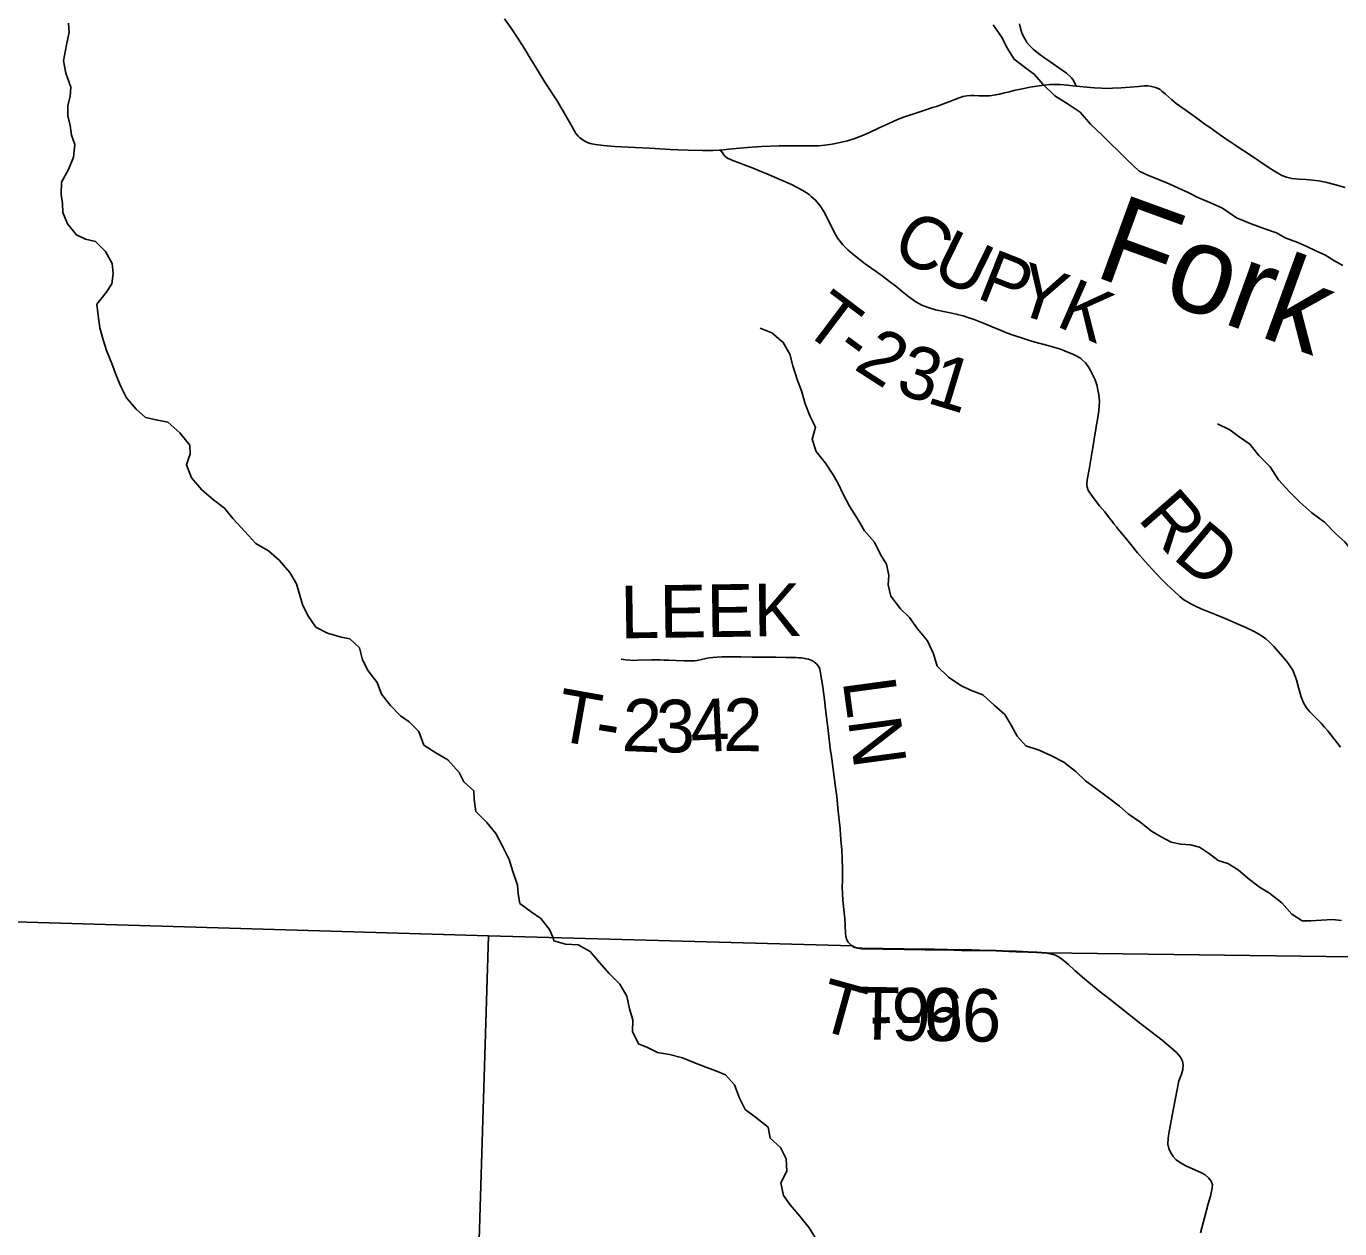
# Model space of a CAD drawing. Extents: x 0 to 34, y 0 to 22.
# Drawn here: x 3.856 to 5.272, y 15.28 to 16.577 of the extents above; entities that cross this region are included whole.
import ezdxf

# ---------------------------------------------------------------- set-up
doc = ezdxf.new("R2010")
doc.units = 0
for name, color, linetype in [('GM_X_Corporation', 7, 'Continuous'), ('GM_X_County_Road', 7, 'Continuous'), ('GM_X_Minor_River', 7, 'Continuous'), ('GM_X_Minor_River_Text', 7, 'Continuous'), ('GM_X_Township_Road', 7, 'Continuous'), ('GM_X_Township_Road_Text', 7, 'Continuous')]:
    doc.layers.add(name, color=color, linetype=linetype)

msp = doc.modelspace()

# ---------------------------------------------------------------- linework, layer by layer
at = {"layer": 'GM_X_Corporation'}
for points in [[(2.9828, 15.6366), (4.3545, 15.5959), (4.7469, 15.5851), (4.7491, 15.5839), (4.752, 15.583), (4.7567, 15.5825), (4.8249, 15.5815), (4.8348, 15.5815), (4.8639, 15.5808), (4.8707, 15.5807), (4.875, 15.5807), (4.8836, 15.5806), (4.9014, 15.5802), (4.9151, 15.5796), (4.9231, 15.5793), (4.936, 15.5788), (4.9453, 15.5784), (4.9558, 15.5778), (5.3123, 15.5731), (5.3483, 15.5723), (5.3453, 15.7118), (5.3543, 16.3597), (5.3699, 17.5116)], [(5.3699, 17.5116), (5.3543, 16.3597), (5.3453, 15.7118), (5.3483, 15.5723), (5.3123, 15.5731), (4.9558, 15.5778), (4.9453, 15.5784), (4.936, 15.5788), (4.9231, 15.5793), (4.9151, 15.5796), (4.9014, 15.5802), (4.8836, 15.5806), (4.875, 15.5807), (4.8707, 15.5807), (4.8639, 15.5808), (4.8348, 15.5815), (4.8249, 15.5815), (4.7567, 15.5825), (4.752, 15.583), (4.7491, 15.5839), (4.7469, 15.5851), (4.3545, 15.5959), (2.9828, 15.6366)], [(2.9828, 15.6366), (4.3545, 15.5959), (4.7469, 15.5851), (4.7491, 15.5839), (4.752, 15.583), (4.7567, 15.5825), (4.8249, 15.5815), (4.8348, 15.5815), (4.8639, 15.5808), (4.8707, 15.5807), (4.875, 15.5807), (4.8836, 15.5806), (4.9014, 15.5802), (4.9151, 15.5796), (4.9231, 15.5793), (4.936, 15.5788), (4.9453, 15.5784), (4.9558, 15.5778), (5.3123, 15.5731), (5.3483, 15.5723), (5.3453, 15.7118), (5.3543, 16.3597), (5.3699, 17.5116)], [(5.3123, 15.5731), (4.9558, 15.5778), (4.9453, 15.5784), (4.936, 15.5788), (4.9231, 15.5793), (4.9151, 15.5796), (4.9014, 15.5802), (4.8836, 15.5806), (4.875, 15.5807), (4.8707, 15.5807), (4.8639, 15.5808), (4.8348, 15.5815), (4.8249, 15.5815), (4.7567, 15.5825), (4.752, 15.583), (4.7491, 15.5839), (4.7469, 15.5851), (4.3545, 15.5959), (4.3388, 15.081)]]:
    msp.add_lwpolyline(points, dxfattribs=at)
msp.add_lwpolyline([(2.1, 15.6606), (2.1, 14.1), (4.3124, 14.1), (4.324, 14.5949), (4.3241, 14.5964), (4.3352, 14.9629), (4.3354, 14.967), (4.3388, 15.081), (4.3545, 15.5959), (2.9828, 15.6366), (2.9609, 15.6375)], close=True, dxfattribs=at)
at = {"layer": 'GM_X_County_Road'}
for points in [[(4.3716, 16.5846), (4.3788, 16.5746), (4.3861, 16.5638), (4.3905, 16.557), (4.3938, 16.5517), (4.3996, 16.5421), (4.406, 16.5318), (4.4153, 16.5162), (4.4285, 16.496), (4.4428, 16.4712), (4.4467, 16.4641), (4.4488, 16.4609), (4.4513, 16.4581), (4.4526, 16.4568), (4.4553, 16.4543), (4.4583, 16.4525), (4.4613, 16.4512), (4.4642, 16.4502), (4.4697, 16.449), (4.4784, 16.4479), (4.4902, 16.4471), (4.5051, 16.4462), (4.528, 16.445), (4.5336, 16.4447), (4.5503, 16.4438), (4.559, 16.4434), (4.5696, 16.443), (4.5851, 16.4425), (4.5963, 16.4425), (4.6031, 16.4429), (4.6045, 16.4431)], [(4.6045, 16.4431), (4.6135, 16.4441), (4.6252, 16.4453), (4.6338, 16.446), (4.6486, 16.4468), (4.6676, 16.4476), (4.6732, 16.4477), (4.6892, 16.4478), (4.7021, 16.4476), (4.7101, 16.4478), (4.7169, 16.4484), (4.7248, 16.4496), (4.7333, 16.4512), (4.7412, 16.4531), (4.7483, 16.4553), (4.757, 16.4585), (4.7644, 16.4617), (4.7756, 16.467), (4.7852, 16.4715), (4.7914, 16.4743), (4.797, 16.4767), (4.8027, 16.479), (4.8172, 16.4837), (4.8237, 16.4857), (4.833, 16.4888), (4.8372, 16.4902), (4.8506, 16.495), (4.8569, 16.4976), (4.8616, 16.4994), (4.8657, 16.5007), (4.87, 16.5015), (4.8743, 16.5018), (4.878, 16.5018), (4.8829, 16.5014), (4.8878, 16.5014), (4.8909, 16.5015), (4.8921, 16.5015), (4.8945, 16.5016), (4.8969, 16.5019), (4.901, 16.5025), (4.9052, 16.5035), (4.9105, 16.5047), (4.9159, 16.506), (4.9206, 16.5072), (4.9242, 16.508), (4.9332, 16.5099), (4.938, 16.5108), (4.9478, 16.5124), (4.9533, 16.5132), (4.9594, 16.5138), (4.9644, 16.5139), (4.9706, 16.5138), (4.9786, 16.5131), (4.9842, 16.5125), (4.9877, 16.5121)], [(4.9877, 16.5121), (4.9953, 16.5113), (5.0071, 16.5102), (5.0151, 16.5097), (5.0201, 16.5096), (5.0269, 16.5097), (5.0362, 16.5102), (5.0461, 16.5109), (5.0548, 16.5116), (5.0614, 16.5123), (5.0651, 16.5123), (5.069, 16.5117), (5.0732, 16.5106), (5.076, 16.5094), (5.0782, 16.5082), (5.0802, 16.5067), (5.0839, 16.5035), (5.0904, 16.4976), (5.0957, 16.4933), (5.0992, 16.4907), (5.1027, 16.4882), (5.1123, 16.4813), (5.1148, 16.4795), (5.1234, 16.4733), (5.1279, 16.4701), (5.1315, 16.4676), (5.1432, 16.4593), (5.1539, 16.4519), (5.155, 16.4513), (5.1591, 16.4485), (5.1768, 16.4369), (5.1927, 16.4261), (5.1986, 16.422), (5.2034, 16.4191), (5.2093, 16.4157), (5.2143, 16.4137), (5.2203, 16.4124), (5.2278, 16.4117), (5.2351, 16.4113), (5.2425, 16.4106), (5.2492, 16.4098), (5.2565, 16.4083), (5.2662, 16.406), (5.2776, 16.4028)]]:
    msp.add_lwpolyline(points, dxfattribs=at)
at = {"layer": 'GM_X_Minor_River'}
for points in [[(4.4241, 15.5938), (4.4204, 15.6027), (4.4109, 15.6147), (4.4006, 15.6219), (4.3884, 15.6309), (4.3864, 15.6411), (4.3856, 15.6506), (4.3809, 15.6654), (4.3767, 15.6782), (4.3694, 15.6933), (4.3624, 15.7062), (4.3529, 15.7183), (4.341, 15.7299), (4.3391, 15.7428), (4.3386, 15.7523), (4.3279, 15.7621), (4.3229, 15.7719), (4.3107, 15.7858), (4.2978, 15.7933), (4.2848, 15.8016), (4.2794, 15.8163), (4.2691, 15.8265), (4.2596, 15.8333), (4.2489, 15.8442), (4.2393, 15.8566), (4.2347, 15.8691), (4.2247, 15.8815), (4.2189, 15.8936), (4.2154, 15.9065), (4.2051, 15.9163), (4.1956, 15.9181), (4.1812, 15.9222), (4.1683, 15.9289), (4.1598, 15.9414), (4.1541, 15.9531), (4.1509, 15.9644), (4.1475, 15.9754), (4.1405, 15.9875), (4.1291, 16.0011), (4.1173, 16.0112), (4.1039, 16.0191), (4.0921, 16.0319), (4.0791, 16.0458), (4.0699, 16.0571), (4.0581, 16.0661), (4.0455, 16.0767), (4.0344, 16.0899), (4.029, 16.1039), (4.0331, 16.1157), (4.0327, 16.1251), (4.0219, 16.1383), (4.009, 16.1496), (3.9964, 16.1522), (3.9851, 16.1547), (3.9748, 16.1638), (3.9644, 16.1758), (3.9583, 16.1883), (3.9536, 16.1993), (3.9486, 16.2129), (3.9428, 16.2269), (3.9386, 16.2409), (3.9358, 16.2515), (3.9338, 16.2648), (3.9326, 16.2769), (3.9424, 16.2895), (3.9488, 16.299), (3.9502, 16.31), (3.949, 16.3207), (3.9417, 16.3339), (3.931, 16.3444), (3.9204, 16.347), (3.9105, 16.3518), (3.9009, 16.3635), (3.8959, 16.3756), (3.8954, 16.3855), (3.8942, 16.395), (3.8945, 16.4083), (3.902, 16.422), (3.9072, 16.4353), (3.9086, 16.449), (3.9052, 16.4592), (3.9039, 16.4694), (3.9012, 16.48), (3.9011, 16.4906), (3.9037, 16.5013), (3.9044, 16.5108), (3.899, 16.5259), (3.8966, 16.5392), (3.8999, 16.5567), (3.9025, 16.5703), (3.902, 16.5798)], [(5.2751, 16.3188), (5.2656, 16.324), (5.2557, 16.33), (5.2462, 16.3345), (5.2363, 16.339), (5.2268, 16.3434), (5.2131, 16.3486), (5.2036, 16.3539), (5.1899, 16.3587), (5.1762, 16.3635), (5.1606, 16.3702), (5.1454, 16.3804), (5.1317, 16.3867), (5.1188, 16.3919), (5.1092, 16.3971), (5.0982, 16.402), (5.088, 16.4065), (5.0784, 16.4106), (5.0651, 16.4161), (5.0556, 16.4202), (5.0423, 16.433), (5.0159, 16.459), (5.0033, 16.471), (4.9922, 16.4839), (4.9793, 16.4925), (4.9648, 16.5015), (4.9518, 16.5143), (4.943, 16.5244), (4.9331, 16.5316), (4.9209, 16.541), (4.9129, 16.5538), (4.9079, 16.564), (4.8983, 16.578)], [(5.2737, 15.6126), (5.2639, 15.6136), (5.2521, 15.6128), (5.2407, 15.6123), (5.2313, 15.6122), (5.2202, 15.6193), (5.2095, 15.6314), (5.1962, 15.6419), (5.1855, 15.6483), (5.1726, 15.658), (5.1623, 15.6671), (5.1512, 15.6738), (5.1409, 15.6771), (5.1314, 15.6843), (5.1208, 15.6914), (5.1109, 15.694), (5.1006, 15.6947), (5.09, 15.6968), (5.0794, 15.7028), (5.0691, 15.7088), (5.0565, 15.719), (5.0439, 15.7276), (5.0344, 15.7359), (5.0226, 15.7449), (5.0073, 15.7561), (4.9978, 15.7629), (4.9879, 15.7727), (4.9745, 15.7832), (4.9604, 15.7903), (4.9479, 15.7963), (4.9335, 15.8007), (4.9243, 15.8113), (4.9177, 15.823), (4.9108, 15.8347), (4.8994, 15.8448), (4.8872, 15.8557), (4.8739, 15.8609), (4.8636, 15.8658), (4.8503, 15.8748), (4.8381, 15.8868), (4.8342, 15.9001), (4.8276, 15.9141), (4.8169, 15.9269), (4.8081, 15.939), (4.7986, 15.9484), (4.7882, 15.962), (4.7851, 15.9745), (4.7858, 15.9843), (4.7834, 15.9968), (4.7769, 16.007), (4.7704, 16.0203), (4.7597, 16.0327), (4.752, 16.0455), (4.7436, 16.0591), (4.7363, 16.0727), (4.7316, 16.0829), (4.7259, 16.0928), (4.7178, 16.1056), (4.7075, 16.118), (4.7032, 16.1313), (4.7069, 16.1442), (4.7012, 16.1559), (4.6958, 16.1695), (4.6919, 16.1836), (4.6872, 16.1957), (4.6826, 16.2104), (4.6791, 16.2229), (4.6722, 16.2358), (4.66, 16.2459), (4.6474, 16.2511)], [(5.3461, 15.9455), (5.3399, 15.9531), (5.3273, 15.9606), (5.314, 15.9692), (5.3037, 15.9824), (5.2956, 15.9956), (5.2872, 16.0081), (5.2772, 16.0209), (5.2677, 16.0292), (5.2555, 16.042), (5.2418, 16.0521), (5.2288, 16.0634), (5.2181, 16.0743), (5.2059, 16.0875), (5.1967, 16.1015), (5.1848, 16.1139), (5.1749, 16.126), (5.1635, 16.1338), (5.1532, 16.1413), (5.1402, 16.1481)], [(4.7084, 15.2677), (4.7, 15.2813), (4.6901, 15.2938), (4.6795, 15.3059), (4.6723, 15.3161), (4.6696, 15.3298), (4.676, 15.3423), (4.6752, 15.3556), (4.6691, 15.3677), (4.6581, 15.3779), (4.6558, 15.3896), (4.6421, 15.4006), (4.6311, 15.4089), (4.625, 15.421), (4.6196, 15.4354), (4.6098, 15.446), (4.5995, 15.4505), (4.5889, 15.4542), (4.5757, 15.4595), (4.5635, 15.4644), (4.5495, 15.4681), (4.5366, 15.4703), (4.526, 15.4756), (4.5162, 15.4794), (4.5097, 15.493), (4.51, 15.5055), (4.5066, 15.5172), (4.5035, 15.5309), (4.4959, 15.5438), (4.4845, 15.5555), (4.4742, 15.5672), (4.464, 15.5789), (4.4511, 15.5861), (4.4375, 15.5871), (4.425, 15.5905), (4.4241, 15.5938)]]:
    msp.add_lwpolyline(points, dxfattribs=at)
at = {"layer": 'GM_X_Township_Road'}
for points in [[(4.9877, 16.5121), (4.9858, 16.5166), (4.9842, 16.5191), (4.9827, 16.5211), (4.981, 16.5228), (4.9772, 16.526), (4.9692, 16.5319), (4.9604, 16.5378), (4.9542, 16.542), (4.9472, 16.5471), (4.9415, 16.5519), (4.9375, 16.5558), (4.9348, 16.5592), (4.9331, 16.5618), (4.931, 16.5656), (4.9294, 16.5696), (4.9279, 16.5744), (4.9269, 16.5792)], [(4.6045, 16.4431), (4.6073, 16.4389), (4.608, 16.4378), (4.6097, 16.4361), (4.6122, 16.4344), (4.6145, 16.4333), (4.6179, 16.4319), (4.6208, 16.4308), (4.6225, 16.4302), (4.6266, 16.4286), (4.6301, 16.4272), (4.6399, 16.4234), (4.6474, 16.4203), (4.6543, 16.4176), (4.6703, 16.4107), (4.681, 16.4058), (4.6877, 16.4024), (4.6932, 16.3994), (4.7, 16.3951), (4.7024, 16.3932), (4.707, 16.3891), (4.7121, 16.3828), (4.7157, 16.377), (4.7183, 16.3721), (4.7265, 16.3553), (4.731, 16.3479), (4.7364, 16.341), (4.7416, 16.3357), (4.7466, 16.3312), (4.752, 16.3268), (4.7604, 16.3206), (4.7711, 16.313), (4.7786, 16.3075), (4.7865, 16.3015), (4.7934, 16.2962), (4.8002, 16.2907), (4.8075, 16.2849), (4.8151, 16.2795), (4.8216, 16.276), (4.8233, 16.2752), (4.8303, 16.2726), (4.8363, 16.271), (4.8466, 16.2688), (4.8539, 16.2673), (4.86, 16.2659), (4.866, 16.2643), (4.8701, 16.263), (4.8778, 16.2603), (4.8905, 16.2554), (4.8973, 16.2525), (4.9071, 16.2484), (4.9128, 16.2462), (4.9198, 16.2436), (4.9322, 16.2394), (4.9363, 16.2382), (4.9423, 16.2365), (4.9573, 16.2325), (4.9674, 16.2295), (4.9721, 16.2279), (4.9761, 16.2264), (4.9842, 16.2231), (4.9892, 16.2207), (4.9928, 16.2182), (4.9947, 16.2167), (4.9977, 16.2136), (5.0008, 16.2096), (5.0033, 16.2054), (5.0059, 16.2004), (5.0081, 16.1952), (5.0099, 16.19), (5.0113, 16.1846), (5.0123, 16.1791), (5.0128, 16.1729), (5.0126, 16.1666), (5.0118, 16.1592), (5.0083, 16.1384), (5.0053, 16.12), (5.0047, 16.1163), (5.0044, 16.1139), (5.0017, 16.0986), (5, 16.0894), (4.9994, 16.0845), (4.9994, 16.082), (4.9998, 16.0796), (5.0005, 16.0772), (5.0018, 16.0745), (5.0042, 16.0709), (5.0073, 16.067), (5.0131, 16.0597), (5.0185, 16.0529), (5.0223, 16.048), (5.0269, 16.0422), (5.0285, 16.0402), (5.0312, 16.0368), (5.0328, 16.0349), (5.0351, 16.032), (5.0438, 16.0215), (5.054, 16.009), (5.0622, 15.9997), (5.0734, 15.9873), (5.0798, 15.9806), (5.086, 15.9745), (5.0936, 15.9672), (5.0995, 15.9617), (5.1039, 15.9583), (5.1076, 15.956), (5.1113, 15.9538), (5.1163, 15.9514), (5.1226, 15.9486), (5.1387, 15.942), (5.1484, 15.938), (5.1632, 15.9315), (5.1706, 15.9282), (5.178, 15.9249), (5.1834, 15.922), (5.1882, 15.9191), (5.1922, 15.9162), (5.1959, 15.9129), (5.2007, 15.908), (5.2105, 15.8968), (5.2131, 15.8938)], [(4.7472, 15.5845), (4.7454, 15.5858), (4.7438, 15.5872), (4.742, 15.5893), (4.7407, 15.5917), (4.7397, 15.5952), (4.7393, 15.5982), (4.7389, 15.608), (4.7384, 15.6148), (4.7373, 15.624), (4.7366, 15.6314), (4.7363, 15.6345), (4.736, 15.6413), (4.7358, 15.6487), (4.7359, 15.6549), (4.736, 15.6648), (4.736, 15.6679), (4.7355, 15.6797), (4.7351, 15.6884), (4.7343, 15.6995), (4.7333, 15.7112), (4.7316, 15.7271), (4.7309, 15.7339), (4.7298, 15.7462), (4.7292, 15.7512), (4.7286, 15.7561), (4.7259, 15.7758), (4.7237, 15.7918), (4.7232, 15.7955), (4.7216, 15.8078), (4.721, 15.814), (4.7195, 15.8263), (4.7178, 15.8405), (4.7165, 15.8509), (4.7148, 15.8639), (4.7127, 15.8773), (4.712, 15.8813), (4.7116, 15.8836), (4.7108, 15.8854), (4.7097, 15.8872), (4.708, 15.8892), (4.7067, 15.8902), (4.7055, 15.8912), (4.7042, 15.892), (4.7028, 15.8927), (4.7011, 15.8935), (4.6993, 15.8941), (4.697, 15.8947), (4.6939, 15.8952), (4.6913, 15.8955), (4.6886, 15.8957), (4.6861, 15.8959), (4.6748, 15.8962), (4.6642, 15.8963), (4.6531, 15.8964), (4.6388, 15.8965), (4.6264, 15.8966), (4.6128, 15.8967), (4.6058, 15.8966), (4.6004, 15.8964), (4.5963, 15.8962), (4.5924, 15.8957), (4.5887, 15.895), (4.5839, 15.8939), (4.5793, 15.8929), (4.5766, 15.8925), (4.5732, 15.8923), (4.5657, 15.8923), (4.5569, 15.8928), (4.5488, 15.8932), (4.5439, 15.8933), (4.5395, 15.8935), (4.5302, 15.8935), (4.5155, 15.893), (4.5106, 15.8929), (4.5025, 15.8936), (4.4976, 15.8943)], [(5.2131, 15.8938), (5.2149, 15.8916), (5.2182, 15.8871), (5.2211, 15.8823), (5.2231, 15.8778), (5.2252, 15.872), (5.2275, 15.8637), (5.2303, 15.8535), (5.2328, 15.8472), (5.236, 15.8419), (5.2396, 15.8376), (5.243, 15.8339), (5.25, 15.8269), (5.2517, 15.8251), (5.2529, 15.8237), (5.2554, 15.821), (5.2591, 15.8168), (5.2626, 15.8124), (5.2691, 15.8041), (5.2728, 15.7992)], [(4.7472, 15.5845), (4.7493, 15.5834), (4.7522, 15.5825), (4.7569, 15.5819), (4.8251, 15.581), (4.835, 15.581), (4.8561, 15.5805), (4.8641, 15.5803), (4.8709, 15.5802), (4.8752, 15.5802), (4.8838, 15.5801), (4.9016, 15.5797), (4.9153, 15.5791), (4.9233, 15.5787), (4.9362, 15.5782), (4.9455, 15.5779), (4.956, 15.5772)], [(4.956, 15.5772), (4.963, 15.5759), (4.9662, 15.5748), (4.9705, 15.5723), (4.979, 15.5653), (4.9865, 15.5585), (4.997, 15.5494), (5.0137, 15.5357), (5.0245, 15.5273), (5.0575, 15.5011), (5.0804, 15.4835), (5.0903, 15.4753), (5.0958, 15.4703), (5.1003, 15.465), (5.1024, 15.461), (5.1031, 15.457), (5.1029, 15.452), (5.1012, 15.4467), (5.0985, 15.4398), (5.0928, 15.4099), (5.0881, 15.3849), (5.087, 15.3779), (5.0866, 15.3715), (5.0876, 15.3668), (5.0893, 15.3627), (5.0923, 15.3582), (5.0957, 15.3543), (5.1003, 15.3511), (5.1061, 15.3479), (5.1227, 15.3405), (5.1268, 15.3382), (5.1303, 15.3352), (5.1331, 15.3314), (5.1347, 15.3274), (5.1345, 15.3244), (5.1324, 15.3152), (5.1299, 15.3069), (5.126, 15.2921), (5.1216, 15.2756)]]:
    msp.add_lwpolyline(points, dxfattribs=at)

# ---------------------------------------------------------------- texts
at = {"layer": 'GM_X_Minor_River_Text'}
msp.add_text('Fork', height=0.09469, rotation=339.9997, dxfattribs=at).set_placement((5.005, 16.3078))
at = {"layer": 'GM_X_Township_Road_Text'}
for s, height, rotation, p in [('C', 0.0568, 331.9529, (4.7864, 16.3312)), ('U', 0.0568, 333.9173, (4.8295, 16.3083)), ('P', 0.0568, 338.4803, (4.8789, 16.2843)), ('Y', 0.0568, 342.0663, (4.9182, 16.2689)), ('T', 0.0568, 322.9561, (4.6905, 16.2497)), ('K', 0.0568, 336.3506, (4.9644, 16.2541)), ('2', 0.0568, 327.1511, (4.7469, 16.2077)), ('-', 0.0568, 323.7321, (4.7251, 16.2236)), ('3', 0.0568, 342.9013, (4.7917, 16.1815)), ('1', 0.0568, 343.0932, (4.8254, 16.1711)), ('R', 0.0568, 311.0158, (5.0531, 16.0454)), ('D', 0.0568, 319.901, (5.0905, 16.0035)), ('LEEK', 0.05682, 0.8062, (4.4969, 15.9166)), ('LN', 0.05682, 277.7028, (4.7361, 15.8707)), ('T', 0.0568, 349.9614, (4.4245, 15.8073)), ('2', 0.0568, 357.7837, (4.4977, 15.7953)), ('2', 0.0568, 359.5212, (4.6072, 15.7953)), ('3', 0.0568, 359.5163, (4.5346, 15.7939)), ('4', 0.0568, 2.7637, (4.5731, 15.7936)), ('-', 0.0568, 350.7298, (4.4671, 15.7998)), ('T', 0.0568, 344.5147, (4.7062, 15.496)), ('T-96', 0.05682, 358.9575, (4.7504, 15.4844)), ('9', 0.0568, 359.4197, (4.7885, 15.4832)), ('6', 0.0568, 359.5854, (4.8236, 15.4829)), ('-', 0.0568, 1.9734, (4.7658, 15.4825))]:
    msp.add_text(s, height=height, rotation=rotation, dxfattribs=at).set_placement(p)

doc.saveas('drawing.dxf')
